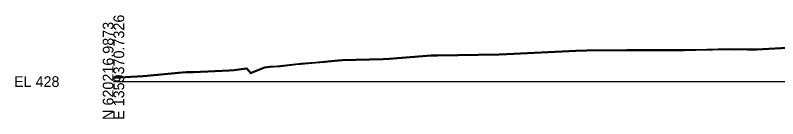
# Model space of a CAD drawing. Extents: x -26 to 803, y -27 to 3586.
# Drawn here: x -25.7 to 173.7, y 490.3 to 517.3 of the extents above; entities that cross this region are included whole.
import ezdxf

# ---------------------------------------------------------------- set-up
doc = ezdxf.new("R2010")
doc.units = 0
for name, color, linetype in [('DESIGN - SHEET - Light Grid', 7, 'Continuous'), ('SURVEY - GROUND - Bottom of Topsoil Layer', 7, 'Continuous'), ('SURVEY - GROUND - Top of Ground', 7, 'Continuous')]:
    doc.layers.add(name, color=color, linetype=linetype)

msp = doc.modelspace()

# ---------------------------------------------------------------- linework, layer by layer
at = {"layer": 'DESIGN - SHEET - Light Grid'}
msp.add_line((0, 500), (400, 500), dxfattribs=at)
at = {"layer": 'SURVEY - GROUND - Bottom of Topsoil Layer'}
for p, q in [((168.28, 508.27), (177.79, 508.8)), ((72.11, 505.87), (83.06, 506.72)), ((83.06, 506.72), (84.71, 506.75)), ((84.71, 506.75), (100.91, 507.02)), ((100.91, 507.02), (102.92, 507.11)), ((102.92, 507.11), (120.96, 507.99)), ((120.96, 507.99), (123.81, 508.05)), ((123.81, 508.05), (134.26, 508.1)), ((134.26, 508.1), (149.22, 508.12)), ((149.22, 508.12), (152.25, 508.17)), ((152.25, 508.17), (161.14, 508.39)), ((161.14, 508.39), (165.86, 508.32)), ((165.86, 508.32), (167.35, 508.3)), ((167.35, 508.3), (168.28, 508.27)), ((48.39, 504.51), (48.99, 504.57)), ((48.99, 504.57), (52.85, 504.86)), ((52.85, 504.86), (55.31, 505.07)), ((55.31, 505.07), (56.96, 505.25)), ((56.96, 505.25), (59.79, 505.5)), ((59.79, 505.5), (70.53, 505.78)), ((70.53, 505.78), (72.11, 505.87)), ((20.92, 502.42), (30.28, 502.78)), ((30.28, 502.78), (31.53, 502.91)), ((31.53, 502.91), (34.8, 503.34)), ((34.8, 503.34), (35.84, 502.15)), ((35.84, 502.15), (39.6, 503.62)), ((39.6, 503.62), (40.87, 503.77)), ((40.87, 503.77), (41.97, 503.82)), ((41.97, 503.82), (43.69, 503.93)), ((43.69, 503.93), (48.39, 504.51)), ((0, 500.91), (7.75, 501.33)), ((7.75, 501.33), (17.97, 502.28)), ((17.97, 502.28), (19.14, 502.36)), ((19.14, 502.36), (20.92, 502.42))]:
    msp.add_line(p, q, dxfattribs=at)
at = {"layer": 'SURVEY - GROUND - Top of Ground'}
msp.add_lwpolyline([(0, 501.16), (7.75, 501.58), (17.97, 502.53), (19.14, 502.61), (20.92, 502.67), (30.28, 503.03), (31.53, 503.16), (34.8, 503.59), (35.84, 502.4), (39.6, 503.87), (40.87, 504.02), (41.97, 504.07), (43.69, 504.18), (48.39, 504.76), (48.99, 504.82), (52.85, 505.11), (55.31, 505.32), (56.96, 505.5), (59.79, 505.75), (70.53, 506.03), (72.11, 506.12), (83.06, 506.97), (84.71, 507), (100.91, 507.27), (102.92, 507.36), (120.96, 508.24), (123.81, 508.3), (134.26, 508.35), (149.22, 508.37), (152.25, 508.42), (161.14, 508.64), (165.86, 508.57), (167.35, 508.55), (168.28, 508.52), (177.79, 509.05)], dxfattribs=at)

# ---------------------------------------------------------------- texts
at = {"layer": 'DESIGN - SHEET - Light Grid'}
for s, p in [('E 1359370.7326', (2.8, 490)), ('N 620216.9873', (0, 490))]:
    msp.add_text(s, height=2.8, rotation=90, dxfattribs=at).set_placement(p)
msp.add_text('EL 428', height=2.8, dxfattribs=at).set_placement((-26, 498.6))

doc.saveas('drawing.dxf')
